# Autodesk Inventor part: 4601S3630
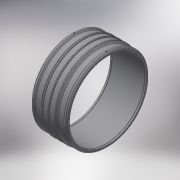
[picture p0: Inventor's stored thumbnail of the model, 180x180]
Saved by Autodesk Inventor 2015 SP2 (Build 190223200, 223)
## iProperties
Created: 2017-06
Part Number: 4601S3630
Material: Generic
Description: PLASSON SUPER LIGHTFIT 630 MM
Document SubType Name: Modeling
Designer: KIM
Mass: 16455.7 g
Surface Area: 15080 cm^2
Volume: 16455.7 cm^3
Density: 1 g/cm^3
Appearance: Default
Author: KIM
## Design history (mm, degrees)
derived "4601S3.ipt"
feature "Solid1::4601S3.ipt"
tag "TaggingFeature1"
body "Solid1"
other parameters: "d14" = 17.6296, "d19" = 3.52592, "d20" = 168 deg, "d22" = 692, "d23" = 693, "d24" = 671.24, "d25" = 135 deg, "d26" = 128, "d27" = 135 deg, "d29" = 346, "d35" = 15, "d39" = 0, "d40" = 4, "d41" = 14, "d42" = 0, "d43" = 135 deg, "d44" = 35.2, "d45" = 12.8, "d46" = 12.8, "d47" = 12.8, "d48" = 679.14, "d49" = 693, "d50" = 3.465, "d51" = 6, "d52" = 0, "D_" = 693, "A_" = 346, "d_2" = 12
